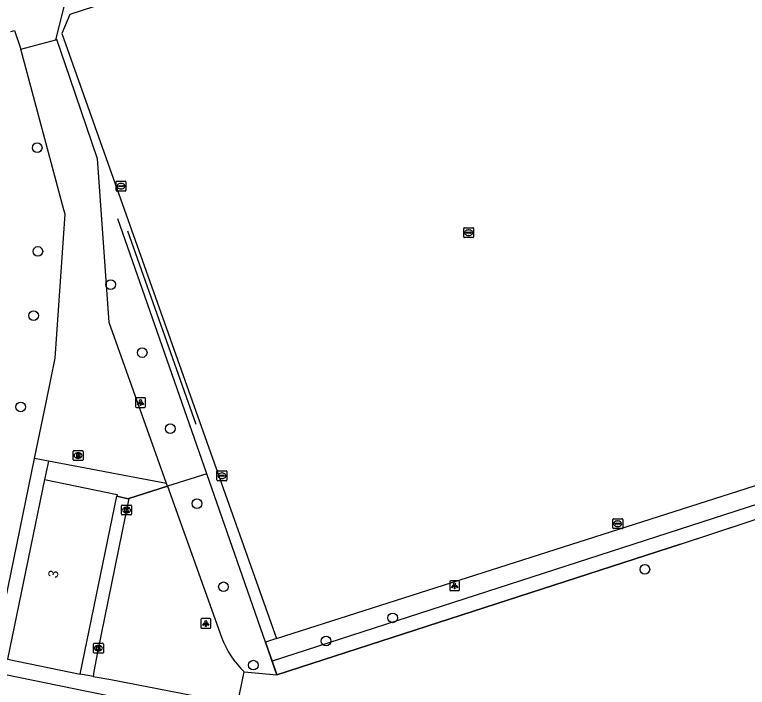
# Model space of a CAD drawing. Extents: x 158087 to 159494, y 382905 to 383981.
# Drawn here: x 159067.8 to 159141.8, y 382951.7 to 383019.7 of the extents above; entities that cross this region are included whole.
import ezdxf

# ---------------------------------------------------------------- set-up
doc = ezdxf.new("R2010")
doc.units = 0
for name, color, linetype in [('IMGEO_Boom', 7, 'Continuous'), ('IMGEO_Brandkraan', 7, 'Continuous'), ('IMGEO_Fietspad_gesloten', 7, 'Continuous'), ('IMGEO_Groenvoorziening', 7, 'Continuous'), ('IMGEO_Haag', 7, 'Continuous'), ('IMGEO_Hek', 7, 'Continuous'), ('IMGEO_Kolk', 7, 'Continuous'), ('IMGEO_Lichtpunt', 7, 'Continuous'), ('IMGEO_Loofbos', 7, 'Continuous'), ('IMGEO_Pand', 7, 'Continuous'), ('IMGEO_Pand_nummerreeks', 7, 'Continuous'), ('IMGEO_Voetpad_gesloten', 7, 'Continuous'), ('IMGEO_Voetpad_open', 7, 'Continuous'), ('IMGEO_Waterleidingput', 7, 'Continuous')]:
    doc.layers.add(name, color=color, linetype=linetype)

msp = doc.modelspace()

# ---------------------------------------------------------------- linework, layer by layer
at = {"layer": 'IMGEO_Boom'}
for centre in [(159070.064, 383006.272), (159070.128, 382995.787), (159077.498, 382992.434), (159069.695, 382989.299), (159080.676, 382985.57), (159068.396, 382980.079), (159083.511, 382977.874), (159086.208, 382970.306), (159131.488, 382963.664), (159088.894, 382961.9), (159105.99, 382958.761), (159099.265, 382956.417), (159091.916, 382953.985)]:
    msp.add_circle(centre, 0.489, dxfattribs=at)
at = {"layer": 'IMGEO_Brandkraan'}
for p, q in [((159073.7, 382974.734), (159073.7, 382975.586)), ((159073.775, 382975.66), (159074.627, 382975.66)), ((159074.188, 382975.44), (159074.213, 382975.44)), ((159074.701, 382975.586), (159074.701, 382974.734)), ((159074.211, 382974.88), (159074.186, 382974.88)), ((159074.627, 382974.66), (159073.775, 382974.66))]:
    msp.add_line(p, q, dxfattribs=at)
for points in [[(159073.7, 382974.734), (159073.7, 382975.586)], [(159073.775, 382975.66), (159074.627, 382975.66)], [(159074.701, 382975.586), (159074.701, 382974.734)], [(159074.048, 382975.36), (159074.048, 382974.96), (159074.261, 382974.96)], [(159074.279, 382975.36), (159074.048, 382975.36)], [(159074.227, 382975.279), (159074.173, 382975.279), (159074.173, 382975.203)], [(159074.173, 382975.203), (159074.226, 382975.203)], [(159074.235, 382975.127), (159074.173, 382975.127), (159074.173, 382975.046)], [(159074.173, 382975.046), (159074.235, 382975.046)], [(159074.627, 382974.66), (159073.775, 382974.66)]]:
    msp.add_lwpolyline(points, dxfattribs=at)
for centre, radius, start, end in [((159073.777, 382975.584), 0.0765, 91.55205, 178.44795), ((159073.777, 382975.584), 0.0765, 91.55205, 178.44795), ((159074.625, 382975.584), 0.0765, 1.55205, 88.44795), ((159074.625, 382975.584), 0.0765, 1.55205, 88.44795), ((159073.777, 382974.736), 0.0765, 181.55205, 268.44795), ((159073.777, 382974.736), 0.0765, 181.55205, 268.44795), ((159074.228, 382975.241), 0.0379, 267.82845, 90.93552), ((159074.236, 382975.086), 0.0404, 269.87594, 90.50774), ((159074.267, 382975.211), 0.251, 268.66757, 293.53466), ((159074.283, 382975.215), 0.145, 59.4692, 91.53667), ((159074.308, 382975.262), 0.0922, 285.51372, 58.15012), ((159074.313, 382975.07), 0.105, 301.31148, 78.98903), ((159074.625, 382974.736), 0.0765, 271.55205, 358.44795), ((159074.625, 382974.736), 0.0765, 271.55205, 358.44795)]:
    msp.add_arc(centre, radius, start, end, dxfattribs=at)
for centre, major_axis, ratio, start_param, end_param in [((159074.187, 382975.16), (-0.387, 0.002), 0.722429, 4.712389, 7.853982), ((159074.212, 382975.16), (-0.39, 0.002), 0.717154, 1.570796, 4.712389)]:
    msp.add_ellipse(centre, major_axis=major_axis, ratio=ratio, start_param=start_param, end_param=end_param, dxfattribs=at)
at = {"layer": 'IMGEO_Fietspad_gesloten'}
for points in [[(159071.934, 383017.153), (159072.865, 383020.766), (159127.162, 383038.33), (159169.93, 383052.158)], [(159067.396, 383018.015), (159067.776, 383018.119), (159068.411, 383016.229)], [(159068.411, 383016.229), (159071.934, 383017.153)]]:
    msp.add_lwpolyline(points, dxfattribs=at)
at = {"layer": 'IMGEO_Groenvoorziening'}
for points in [[(159170.278, 383051.14), (159073.361, 383019.728), (159072.548, 383017.804), (159094.248, 382956.684)], [(159094.248, 382956.684), (159183.625, 382985.215)], [(159163.207, 382960.083), (159160.066, 382944.421), (159158.157, 382934.552), (159135.307, 382939.165), (159083.059, 382949.714), (159075.072, 382951.327), (159065.327, 382953.294), (159069.787, 382974.881)], [(159094.248, 382956.684), (159093.128, 382956.318)]]:
    msp.add_lwpolyline(points, dxfattribs=at)
at = {"layer": 'IMGEO_Haag'}
for points in [[(159184.112, 382983.572), (159093.802, 382954.382)], [(159094.283, 382953.002), (159135.086, 382966.206), (159166.516, 382976.582)], [(159093.802, 382954.382), (159094.283, 382953.002)]]:
    msp.add_lwpolyline(points, dxfattribs=at)
at = {"layer": 'IMGEO_Hek'}
for points in [[(159087.209, 382973.31), (159078.23, 382999.083)], [(159079.204, 382997.866), (159086.108, 382978.341)], [(159135.086, 382966.206), (159167.065, 382976.763)], [(159087.209, 382973.31), (159083.248, 382972.057)], [(159093.128, 382956.318), (159087.209, 382973.31)], [(159083.248, 382972.057), (159079.329, 382970.817)], [(159079.329, 382970.817), (159079.261, 382970.796), (159078.106, 382971.061)], [(159135.086, 382966.206), (159094.283, 382953.002)], [(159094.283, 382953.002), (159093.128, 382956.318)]]:
    msp.add_lwpolyline(points, dxfattribs=at)
at = {"layer": 'IMGEO_Kolk'}
for p, q in [((159078.592, 382969.23), (159078.592, 382970.082)), ((159078.667, 382970.156), (159079.519, 382970.156)), ((159079.08, 382969.936), (159079.105, 382969.936)), ((159079.593, 382970.082), (159079.593, 382969.23)), ((159079.519, 382969.156), (159078.667, 382969.156)), ((159079.103, 382969.376), (159079.078, 382969.376)), ((159075.827, 382956.192), (159076.679, 382956.192)), ((159075.752, 382955.266), (159075.752, 382956.118)), ((159076.24, 382955.972), (159076.265, 382955.972)), ((159076.753, 382956.118), (159076.753, 382955.266)), ((159076.679, 382955.192), (159075.827, 382955.192)), ((159076.263, 382955.412), (159076.238, 382955.412))]:
    msp.add_line(p, q, dxfattribs=at)
for points in [[(159078.592, 382969.23), (159078.592, 382970.082)], [(159078.667, 382970.156), (159079.519, 382970.156)], [(159078.913, 382969.856), (159079.036, 382969.856), (159079.036, 382969.705), (159079.166, 382969.856), (159079.33, 382969.856), (159079.184, 382969.705), (159079.337, 382969.456), (159079.185, 382969.456), (159079.1, 382969.62), (159079.036, 382969.553), (159079.036, 382969.456), (159078.913, 382969.456), (159078.913, 382969.856)], [(159079.593, 382970.082), (159079.593, 382969.23)], [(159079.519, 382969.156), (159078.667, 382969.156)], [(159075.827, 382956.192), (159076.679, 382956.192)], [(159075.752, 382955.266), (159075.752, 382956.118)], [(159076.073, 382955.892), (159076.196, 382955.892), (159076.196, 382955.741), (159076.326, 382955.892), (159076.49, 382955.892), (159076.344, 382955.741), (159076.497, 382955.492), (159076.345, 382955.492), (159076.26, 382955.656), (159076.196, 382955.589), (159076.196, 382955.492), (159076.073, 382955.492), (159076.073, 382955.892)], [(159076.753, 382956.118), (159076.753, 382955.266)], [(159076.679, 382955.192), (159075.827, 382955.192)]]:
    msp.add_lwpolyline(points, dxfattribs=at)
for centre, start, end in [((159078.669, 382970.08), 91.55205, 178.44795), ((159078.669, 382970.08), 91.55205, 178.44795), ((159079.517, 382970.08), 1.55205, 88.44795), ((159079.517, 382970.08), 1.55205, 88.44795), ((159078.669, 382969.232), 181.55205, 268.44795), ((159078.669, 382969.232), 181.55205, 268.44795), ((159079.517, 382969.232), 271.55205, 358.44795), ((159079.517, 382969.232), 271.55205, 358.44795), ((159075.829, 382956.116), 91.55205, 178.44795), ((159075.829, 382956.116), 91.55205, 178.44795), ((159076.677, 382956.116), 1.55205, 88.44795), ((159076.677, 382956.116), 1.55205, 88.44795), ((159075.829, 382955.268), 181.55205, 268.44795), ((159075.829, 382955.268), 181.55205, 268.44795), ((159076.677, 382955.268), 271.55205, 358.44795), ((159076.677, 382955.268), 271.55205, 358.44795)]:
    msp.add_arc(centre, 0.0765, start, end, dxfattribs=at)
for centre, major_axis, ratio, start_param, end_param in [((159079.079, 382969.656), (-0.387, 0.002), 0.722429, 4.712389, 7.853982), ((159079.104, 382969.656), (-0.39, 0.002), 0.717154, 1.570796, 4.712389), ((159076.239, 382955.692), (-0.387, 0.002), 0.722429, 4.712389, 7.853982), ((159076.264, 382955.692), (-0.39, 0.002), 0.717154, 1.570796, 4.712389)]:
    msp.add_ellipse(centre, major_axis=major_axis, ratio=ratio, start_param=start_param, end_param=end_param, dxfattribs=at)
at = {"layer": 'IMGEO_Lichtpunt'}
for p, q in [((159080.014, 382980.915), (159080.014, 382980.108)), ((159080.014, 382980.915), (159080.014, 382980.108)), ((159080.916, 382981.01), (159080.108, 382981.01)), ((159080.916, 382981.01), (159080.108, 382981.01)), ((159081.01, 382980.108), (159081.01, 382980.915)), ((159081.01, 382980.108), (159081.01, 382980.915)), ((159080.108, 382980.014), (159080.916, 382980.014)), ((159080.108, 382980.014), (159080.916, 382980.014)), ((159111.76, 382962.415), (159111.76, 382961.608)), ((159111.76, 382962.415), (159111.76, 382961.608)), ((159112.662, 382962.51), (159111.854, 382962.51)), ((159112.662, 382962.51), (159111.854, 382962.51)), ((159112.756, 382961.608), (159112.756, 382962.415)), ((159112.756, 382961.608), (159112.756, 382962.415)), ((159111.854, 382961.514), (159112.662, 382961.514)), ((159111.854, 382961.514), (159112.662, 382961.514)), ((159086.605, 382958.609), (159086.605, 382957.802)), ((159086.605, 382958.609), (159086.605, 382957.802)), ((159087.507, 382958.704), (159086.699, 382958.704)), ((159087.507, 382958.704), (159086.699, 382958.704)), ((159087.601, 382957.802), (159087.601, 382958.609)), ((159087.601, 382957.802), (159087.601, 382958.609)), ((159086.699, 382957.708), (159087.507, 382957.708)), ((159086.699, 382957.708), (159087.507, 382957.708))]:
    msp.add_line(p, q, dxfattribs=at)
for points in [[(159080.388, 382980.579), (159080.427, 382980.551), (159080.239, 382980.289), (159080.201, 382980.316), (159080.388, 382980.579)], [(159080.49, 382980.531), (159080.537, 382980.531), (159080.537, 382980.209), (159080.49, 382980.209), (159080.49, 382980.531)], [(159080.6, 382980.551), (159080.638, 382980.578), (159080.825, 382980.316), (159080.786, 382980.288), (159080.6, 382980.551)], [(159112.134, 382962.079), (159112.173, 382962.051), (159111.985, 382961.789), (159111.947, 382961.816), (159112.134, 382962.079)], [(159112.236, 382962.031), (159112.283, 382962.031), (159112.283, 382961.709), (159112.236, 382961.709), (159112.236, 382962.031)], [(159112.346, 382962.051), (159112.384, 382962.078), (159112.571, 382961.816), (159112.532, 382961.788), (159112.346, 382962.051)], [(159086.979, 382958.273), (159087.018, 382958.245), (159086.83, 382957.983), (159086.792, 382958.01), (159086.979, 382958.273)], [(159087.081, 382958.225), (159087.128, 382958.225), (159087.128, 382957.903), (159087.081, 382957.903), (159087.081, 382958.225)], [(159087.191, 382958.245), (159087.229, 382958.272), (159087.416, 382958.01), (159087.377, 382957.982), (159087.191, 382958.245)]]:
    msp.add_lwpolyline(points, dxfattribs=at)
for centre in [(159080.513, 382980.713), (159112.259, 382962.213), (159087.104, 382958.407)]:
    msp.add_circle(centre, 0.0994, dxfattribs=at)
for centre, start, end in [((159080.108, 382980.915), 90, 180), ((159080.108, 382980.915), 90, 180), ((159080.916, 382980.915), 0, 90), ((159080.916, 382980.915), 0, 90), ((159080.108, 382980.108), 180, 270), ((159080.108, 382980.108), 180, 270), ((159080.916, 382980.108), 270, 0), ((159080.916, 382980.108), 270, 360), ((159111.854, 382962.415), 90, 180), ((159111.854, 382962.415), 90, 180), ((159112.662, 382962.415), 0, 90), ((159112.662, 382962.415), 0, 90), ((159111.854, 382961.608), 180, 270), ((159111.854, 382961.608), 180, 270), ((159112.662, 382961.608), 270, 0), ((159112.662, 382961.608), 270, 360), ((159086.699, 382958.609), 90, 180), ((159086.699, 382958.609), 90, 180), ((159087.507, 382958.609), 0, 90), ((159087.507, 382958.609), 0, 90), ((159086.699, 382957.802), 180, 270), ((159086.699, 382957.802), 180, 270), ((159087.507, 382957.802), 270, 0), ((159087.507, 382957.802), 270, 360)]:
    msp.add_arc(centre, 0.0946, start, end, dxfattribs=at)
at = {"layer": 'IMGEO_Loofbos'}
for points in [[(159093.128, 382956.318), (159087.209, 382973.31), (159083.248, 382972.057)], [(159093.128, 382956.318), (159093.802, 382954.382)], [(159090.995, 382953.31), (159094.283, 382953.002)]]:
    msp.add_lwpolyline(points, dxfattribs=at)
at = {"layer": 'IMGEO_Pand'}
for points in [[(159070.811, 382972.732), (159067.072, 382954.59), (159074.39, 382953.079)], [(159070.811, 382972.732), (159078.138, 382971.217), (159078.106, 382971.061)], [(159074.39, 382953.079), (159078.106, 382971.061)]]:
    msp.add_lwpolyline(points, dxfattribs=at)
at = {"layer": 'IMGEO_Voetpad_gesloten'}
for points in [[(159083.144, 382972.346), (159077.329, 382988.595), (159076.522, 383000), (159076.157, 383005.152), (159073.395, 383013.268), (159072.059, 383017.187), (159071.934, 383017.153)], [(159069.787, 382974.881), (159070.991, 382980.706), (159071.892, 382985.01), (159072.895, 382999.559), (159072.761, 383000), (159068.411, 383016.229)], [(159071.2, 382974.589), (159069.787, 382974.881)], [(159083.144, 382972.346), (159071.2, 382974.589)], [(159079.329, 382970.817), (159083.248, 382972.057)], [(159083.248, 382972.057), (159088.702, 382956.813)], [(159079.329, 382970.817), (159076.17, 382955.285), (159075.776, 382953.35), (159075.726, 382952.844)], [(159075.726, 382952.844), (159077.508, 382952.534), (159083.398, 382951.38), (159090.317, 382950.025), (159090.995, 382953.31)]]:
    msp.add_lwpolyline(points, dxfattribs=at)
msp.add_arc((159097.21, 382959.88), 9.044, 199.82491, 226.59115, dxfattribs=at)
at = {"layer": 'IMGEO_Voetpad_open'}
for points in [[(159071.2, 382974.589), (159071.113, 382974.126), (159070.811, 382972.732)], [(159083.248, 382972.057), (159083.144, 382972.346)], [(159078.106, 382971.061), (159079.261, 382970.796), (159079.329, 382970.817)], [(159075.726, 382952.844), (159075.4, 382952.901), (159074.39, 382953.079)]]:
    msp.add_lwpolyline(points, dxfattribs=at)
at = {"layer": 'IMGEO_Waterleidingput'}
for p, q in [((159078.109, 383002.888), (159078.961, 383002.888)), ((159078.034, 383001.962), (159078.034, 383002.814)), ((159078.293, 383002.382), (159078.293, 383002.394)), ((159078.731, 383002.345), (159078.333, 383002.345)), ((159078.336, 383002.431), (159078.734, 383002.431)), ((159078.545, 383002.108), (159078.52, 383002.108)), ((159078.522, 383002.668), (159078.547, 383002.668)), ((159078.777, 383002.394), (159078.777, 383002.382)), ((159079.035, 383002.814), (159079.035, 383001.962)), ((159078.961, 383001.888), (159078.109, 383001.888)), ((159113.175, 382997.256), (159113.175, 382998.108)), ((159113.25, 382998.182), (159114.102, 382998.182)), ((159113.434, 382997.676), (159113.434, 382997.688)), ((159113.477, 382997.725), (159113.875, 382997.725)), ((159113.663, 382997.962), (159113.688, 382997.962)), ((159113.918, 382997.688), (159113.918, 382997.676)), ((159114.176, 382998.108), (159114.176, 382997.256)), ((159114.102, 382997.182), (159113.25, 382997.182)), ((159113.872, 382997.639), (159113.474, 382997.639)), ((159113.686, 382997.402), (159113.661, 382997.402)), ((159088.237, 382972.695), (159088.237, 382973.547)), ((159088.312, 382973.621), (159089.164, 382973.621)), ((159088.725, 382973.401), (159088.75, 382973.401)), ((159089.238, 382973.547), (159089.238, 382972.695)), ((159089.164, 382972.621), (159088.312, 382972.621)), ((159088.496, 382973.115), (159088.496, 382973.127)), ((159088.934, 382973.078), (159088.536, 382973.078)), ((159088.539, 382973.164), (159088.937, 382973.164)), ((159088.748, 382972.841), (159088.723, 382972.841)), ((159088.98, 382973.127), (159088.98, 382973.115)), ((159128.324, 382968.776), (159129.176, 382968.776)), ((159128.249, 382967.85), (159128.249, 382968.702)), ((159128.508, 382968.27), (159128.508, 382968.282)), ((159128.946, 382968.233), (159128.548, 382968.233)), ((159128.551, 382968.319), (159128.949, 382968.319)), ((159128.737, 382968.556), (159128.762, 382968.556)), ((159128.992, 382968.282), (159128.992, 382968.27)), ((159129.25, 382968.702), (159129.25, 382967.85)), ((159129.176, 382967.776), (159128.324, 382967.776)), ((159128.76, 382967.996), (159128.735, 382967.996))]:
    msp.add_line(p, q, dxfattribs=at)
for points in [[(159078.109, 383002.888), (159078.961, 383002.888)], [(159078.034, 383001.962), (159078.034, 383002.814)], [(159079.035, 383002.814), (159079.035, 383001.962)], [(159078.961, 383001.888), (159078.109, 383001.888)], [(159113.175, 382997.256), (159113.175, 382998.108)], [(159113.25, 382998.182), (159114.102, 382998.182)], [(159114.176, 382998.108), (159114.176, 382997.256)], [(159114.102, 382997.182), (159113.25, 382997.182)], [(159088.237, 382972.695), (159088.237, 382973.547)], [(159088.312, 382973.621), (159089.164, 382973.621)], [(159089.238, 382973.547), (159089.238, 382972.695)], [(159089.164, 382972.621), (159088.312, 382972.621)], [(159128.324, 382968.776), (159129.176, 382968.776)], [(159128.249, 382967.85), (159128.249, 382968.702)], [(159129.25, 382968.702), (159129.25, 382967.85)], [(159129.176, 382967.776), (159128.324, 382967.776)]]:
    msp.add_lwpolyline(points, dxfattribs=at)
for centre, radius, start, end in [((159078.111, 383002.812), 0.0765, 91.55205, 178.44795), ((159078.111, 383002.812), 0.0765, 91.55205, 178.44795), ((159078.959, 383002.812), 0.0765, 1.55205, 88.44795), ((159078.959, 383002.812), 0.0765, 1.55205, 88.44795), ((159078.333, 383002.391), 0.0403, 85.87752, 175.75265), ((159078.33, 383002.381), 0.0366, 178.93798, 274.71019), ((159078.734, 383002.388), 0.043, 264.86636, 352.45326), ((159078.738, 383002.393), 0.0386, 1.73085, 96.63898), ((159078.111, 383001.964), 0.0765, 181.55205, 268.44795), ((159078.111, 383001.964), 0.0765, 181.55205, 268.44795), ((159078.959, 383001.964), 0.0765, 271.55205, 358.44795), ((159078.959, 383001.964), 0.0765, 271.55205, 358.44795), ((159113.252, 382998.106), 0.0765, 91.55205, 178.44795), ((159113.252, 382998.106), 0.0765, 91.55205, 178.44795), ((159113.474, 382997.685), 0.0403, 85.87752, 175.75265), ((159113.471, 382997.675), 0.0366, 178.93798, 274.71019), ((159113.875, 382997.682), 0.043, 264.86636, 352.45326), ((159113.879, 382997.687), 0.0386, 1.73085, 96.63898), ((159114.1, 382998.106), 0.0765, 1.55205, 88.44795), ((159114.1, 382998.106), 0.0765, 1.55205, 88.44795), ((159113.252, 382997.258), 0.0765, 181.55205, 268.44795), ((159113.252, 382997.258), 0.0765, 181.55205, 268.44795), ((159114.1, 382997.258), 0.0765, 271.55205, 358.44795), ((159114.1, 382997.258), 0.0765, 271.55205, 358.44795), ((159088.314, 382973.545), 0.0765, 91.55205, 178.44795), ((159088.314, 382973.545), 0.0765, 91.55205, 178.44795), ((159089.162, 382973.545), 0.0765, 1.55205, 88.44795), ((159089.162, 382973.545), 0.0765, 1.55205, 88.44795), ((159088.314, 382972.697), 0.0765, 181.55205, 268.44795), ((159088.314, 382972.697), 0.0765, 181.55205, 268.44795), ((159088.536, 382973.124), 0.0403, 85.87752, 175.75265), ((159088.533, 382973.114), 0.0366, 178.93798, 274.71019), ((159088.937, 382973.121), 0.043, 264.86636, 352.45326), ((159088.941, 382973.126), 0.0386, 1.73085, 96.63898), ((159089.162, 382972.697), 0.0765, 271.55205, 358.44795), ((159089.162, 382972.697), 0.0765, 271.55205, 358.44795), ((159128.326, 382968.7), 0.0765, 91.55205, 178.44795), ((159128.326, 382968.7), 0.0765, 91.55205, 178.44795), ((159129.174, 382968.7), 0.0765, 1.55205, 88.44795), ((159129.174, 382968.7), 0.0765, 1.55205, 88.44795), ((159128.548, 382968.279), 0.0403, 85.87752, 175.75265), ((159128.545, 382968.269), 0.0366, 178.93798, 274.71019), ((159128.949, 382968.276), 0.043, 264.86636, 352.45326), ((159128.953, 382968.281), 0.0386, 1.73085, 96.63898), ((159128.326, 382967.852), 0.0765, 181.55205, 268.44795), ((159128.326, 382967.852), 0.0765, 181.55205, 268.44795), ((159129.174, 382967.852), 0.0765, 271.55205, 358.44795), ((159129.174, 382967.852), 0.0765, 271.55205, 358.44795)]:
    msp.add_arc(centre, radius, start, end, dxfattribs=at)
for centre, major_axis, ratio, start_param, end_param in [((159078.521, 383002.388), (-0.387, 0.002), 0.722429, 4.712389, 7.853982), ((159078.546, 383002.388), (-0.39, 0.002), 0.717154, 1.570796, 4.712389), ((159113.662, 382997.682), (-0.387, 0.002), 0.722429, 4.712389, 7.853982), ((159113.687, 382997.682), (-0.39, 0.002), 0.717154, 1.570796, 4.712389), ((159088.724, 382973.121), (-0.387, 0.002), 0.722429, 4.712389, 7.853982), ((159088.749, 382973.121), (-0.39, 0.002), 0.717154, 1.570796, 4.712389), ((159128.736, 382968.276), (-0.387, 0.002), 0.722429, 4.712389, 7.853982), ((159128.761, 382968.276), (-0.39, 0.002), 0.717154, 1.570796, 4.712389)]:
    msp.add_ellipse(centre, major_axis=major_axis, ratio=ratio, start_param=start_param, end_param=end_param, dxfattribs=at)

# ---------------------------------------------------------------- texts
at = {"layer": 'IMGEO_Pand_nummerreeks'}
msp.add_text('3', height=1, rotation=78.3546, dxfattribs=at).set_placement((159072.099, 382962.729))

doc.saveas('drawing.dxf')
